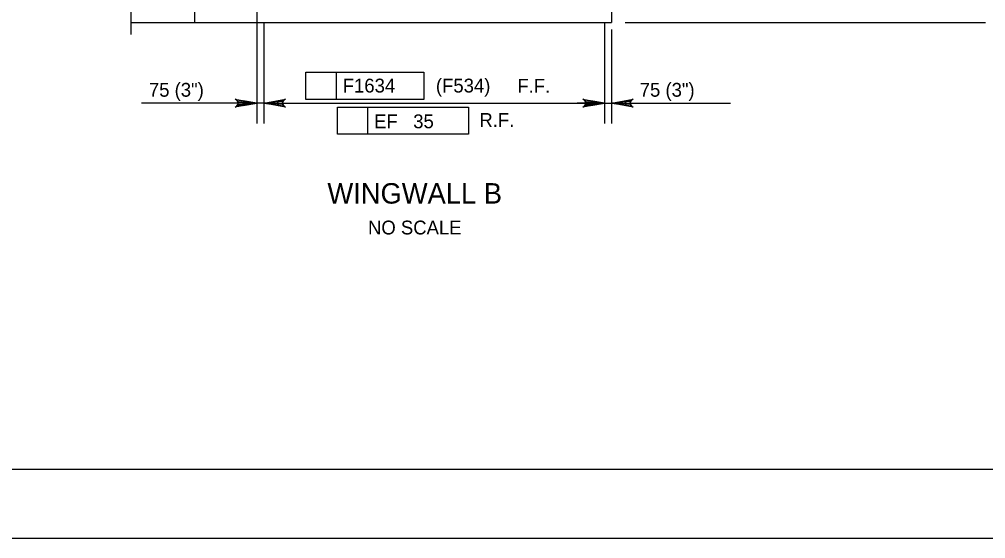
# Model space of a CAD drawing. Extents: x 638340 to 640241, y 295465 to 298435.
# Drawn here: x 638776.1 to 638985.6, y 295465.5 to 295578 of the extents above; entities that cross this region are included whole.
import ezdxf

# ---------------------------------------------------------------- set-up
doc = ezdxf.new("R2010")
doc.units = 0
for name, color, linetype in [('10', 7, 'Continuous'), ('2', 7, 'Continuous'), ('3', 7, 'Continuous'), ('4', 7, 'Continuous'), ('PLT-BNDY', 7, 'Continuous')]:
    doc.layers.add(name, color=color, linetype=linetype)

msp = doc.modelspace()

# ---------------------------------------------------------------- linework, layer by layer
at = {"layer": '10'}
for p, q in [((638904.47, 295651.76), (638904.47, 295577.33)), ((638814.1, 295589.63), (638814.1, 295577.33)), ((638800.3, 295577.33), (638904.47, 295577.33))]:
    msp.add_line(p, q, dxfattribs=at)
at = {"layer": '2'}
msp.add_line((639261.46, 295480.46), (638475.46, 295480.46), dxfattribs=at)
at = {"layer": '3'}
msp.add_line((638800.3, 295605.28), (638800.3, 295574.7), dxfattribs=at)
at = {"layer": '4'}
for p, q in [((638827.57, 295588.09), (638827.57, 295555.42)), ((638829.11, 295577.33), (638829.11, 295555.42)), ((638902.93, 295577.33), (638902.93, 295555.42)), ((638907.46, 295577.33), (638985.53, 295577.33)), ((638904.47, 295575.79), (638904.47, 295555.42)), ((638838.24, 295566.57), (638863.78, 295566.57)), ((638838.24, 295560.66), (638838.24, 295566.57)), ((638844.84, 295560.66), (638844.84, 295566.57)), ((638863.78, 295566.57), (638863.78, 295560.66)), ((638863.78, 295560.66), (638838.24, 295560.66)), ((638821.67, 295559.85), (638802.59, 295559.85)), ((638824.62, 295559.85), (638821.67, 295559.85)), ((638829.11, 295559.85), (638827.57, 295559.85)), ((638832.06, 295559.85), (638899.98, 295559.85)), ((638832.06, 295559.85), (638835.02, 295559.85)), ((638845.05, 295559), (638873.47, 295559)), ((638845.05, 295553.1), (638845.05, 295559)), ((638851.64, 295553.1), (638851.64, 295559)), ((638873.47, 295559), (638873.47, 295553.1)), ((638899.98, 295559.85), (638897.03, 295559.85)), ((638902.93, 295559.85), (638904.47, 295559.85)), ((638907.42, 295559.85), (638910.38, 295559.85)), ((638910.38, 295559.85), (638930.23, 295559.85)), ((638873.47, 295553.1), (638845.05, 295553.1))]:
    msp.add_line(p, q, dxfattribs=at)
for points in [[(638827.57, 295559.85), (638822.91, 295558.98), (638823.27, 295559.23), (638823.46, 295559.54), (638823.51, 295559.85), (638823.46, 295560.16), (638823.27, 295560.48), (638822.91, 295560.72), (638827.57, 295559.85), (638823.27, 295560.48), (638823.46, 295560.16), (638827.57, 295559.85), (638823.51, 295559.85), (638823.46, 295559.54), (638827.57, 295559.85), (638823.27, 295559.23)], [(638829.11, 295559.85), (638833.77, 295560.72), (638833.41, 295560.48), (638833.23, 295560.16), (638833.17, 295559.85), (638833.23, 295559.54), (638833.41, 295559.23), (638833.77, 295558.98), (638829.11, 295559.85), (638833.41, 295559.23), (638833.23, 295559.54), (638829.11, 295559.85), (638833.17, 295559.85), (638833.23, 295560.16), (638829.11, 295559.85), (638833.41, 295560.48)], [(638902.93, 295559.85), (638898.27, 295558.98), (638898.63, 295559.23), (638898.82, 295559.54), (638898.87, 295559.85), (638898.82, 295560.16), (638898.63, 295560.48), (638898.27, 295560.72), (638902.93, 295559.85), (638898.63, 295560.48), (638898.82, 295560.16), (638902.93, 295559.85), (638898.87, 295559.85), (638898.82, 295559.54), (638902.93, 295559.85), (638898.63, 295559.23)], [(638904.47, 295559.85), (638909.13, 295560.72), (638908.77, 295560.48), (638908.59, 295560.16), (638908.53, 295559.85), (638908.59, 295559.54), (638908.77, 295559.23), (638909.13, 295558.98), (638904.47, 295559.85), (638908.77, 295559.23), (638908.59, 295559.54), (638904.47, 295559.85), (638908.53, 295559.85), (638908.59, 295560.16), (638904.47, 295559.85), (638908.77, 295560.48)]]:
    msp.add_lwpolyline(points, dxfattribs=at)
for points in [[(638824.62, 295560.34), (638824.62, 295559.36), (638827.57, 295559.85)], [(638832.06, 295560.34), (638832.06, 295559.36), (638829.11, 295559.85)], [(638899.98, 295560.34), (638899.98, 295559.36), (638902.93, 295559.85)], [(638907.42, 295560.34), (638907.42, 295559.36), (638904.47, 295559.85)]]:
    msp.add_lwpolyline(points, close=True, dxfattribs=at)
at = {"layer": 'PLT-BNDY'}
msp.add_lwpolyline([(638435.46, 296059.46), (639276.46, 296059.46), (639276.46, 295465.46), (638435.46, 295465.46)], close=True, dxfattribs=at)

# ---------------------------------------------------------------- texts
at = {"layer": '4'}
for s, height, p in [('F1634', 3, (638846.2, 295562.14)), ('(F534)', 3, (638866.4, 295562.14)), ('F.F.', 3, (638884.05, 295562.08)), ('75 (3")', 3, (638804.19, 295561.23)), ('75 (3")', 3, (638910.58, 295561.23)), ('EF   35', 3, (638853.01, 295554.4)), ('R.F.', 3, (638875.82, 295554.69)), ('WINGWALL B', 4.429, (638842.89, 295538.07)), ('NO SCALE', 3, (638851.68, 295531.38))]:
    msp.add_text(s, height=height, dxfattribs=at).set_placement(p)

doc.saveas('drawing.dxf')
